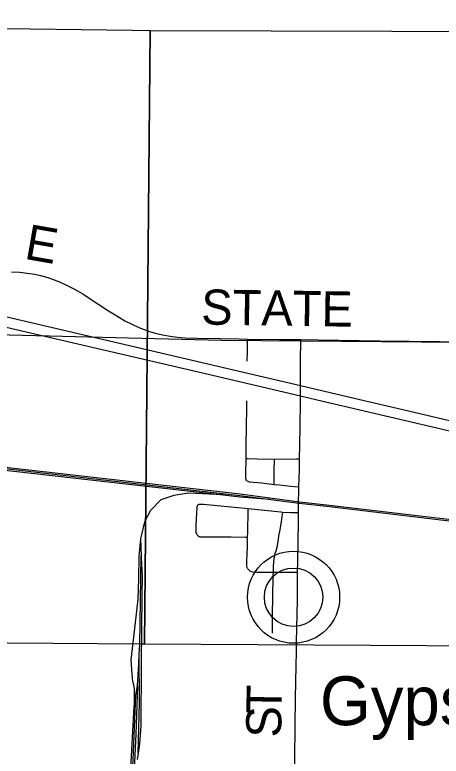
# Model space of a CAD drawing. Extents: x 63.4 to 97.4, y 0.4 to 22.4.
# Drawn here: x 66.497 to 67.186, y 15.396 to 16.594 of the extents above; entities that cross this region are included whole.
import ezdxf

# ---------------------------------------------------------------- set-up
doc = ezdxf.new("R2010")
doc.units = 0
for name, color, linetype in [('GM_X_County_Road', 7, 'Continuous'), ('GM_X_County_Road_Text', 7, 'Continuous'), ('GM_X_Rail_Line', 7, 'Continuous'), ('GM_X_Section', 7, 'Continuous'), ('GM_X_State_Route', 7, 'Continuous'), ('GM_X_Township_Road', 7, 'Continuous'), ('GM_X_Unincorporated', 7, 'Continuous'), ('GM_X_Unincorporated_Location', 7, 'Continuous'), ('GM_X_Unincorporated_Text', 7, 'Continuous')]:
    doc.layers.add(name, color=color, linetype=linetype)

msp = doc.modelspace()

# ---------------------------------------------------------------- linework, layer by layer
at = {"layer": 'GM_X_County_Road'}
for points in [[(66.4923, 16.1792), (66.5048, 16.1785), (66.5172, 16.1771), (66.5295, 16.175), (66.5387, 16.173), (66.5507, 16.1697), (66.5596, 16.1668), (66.5684, 16.1633), (66.5798, 16.1582), (66.5936, 16.1511), (66.6072, 16.1434), (66.6178, 16.1367), (66.6488, 16.116), (66.662, 16.1078), (66.6754, 16.1001), (66.6864, 16.0943), (66.6977, 16.0892), (66.7063, 16.0857), (66.7151, 16.0827), (66.724, 16.0801), (66.7361, 16.0772), (66.7483, 16.0749), (66.7605, 16.0732), (66.7729, 16.0722), (66.7915, 16.0716), (66.8288, 16.0712), (66.8599, 16.0706), (66.8734, 16.0704)], [(66.8734, 16.0704), (66.9253, 16.0698), (66.9501, 16.0695), (66.9594, 16.0695)], [(66.9575, 15.877), (66.958, 15.8999), (66.9582, 15.9278), (66.9588, 15.9711), (66.9588, 15.9785), (66.9589, 15.9953), (66.9589, 16.0178), (66.9592, 16.0364), (66.9594, 16.067), (66.9594, 16.0695)], [(66.9594, 16.0695), (66.9875, 16.0692), (67.087, 16.0673), (67.2799, 16.0651), (67.3097, 16.0648)], [(66.9565, 15.8314), (66.9572, 15.8595), (66.9575, 15.877)], [(66.9555, 15.7901), (66.9557, 15.8005), (66.9565, 15.8314)], [(66.9544, 15.694), (66.9549, 15.7105), (66.9555, 15.7757), (66.9555, 15.7901)], [(66.9526, 15.5807), (66.954, 15.6491), (66.9544, 15.694)], [(66.9518, 15.5428), (66.9523, 15.5646), (66.9526, 15.5807)], [(66.9495, 15.3439), (66.95, 15.3907), (66.9503, 15.4464), (66.9508, 15.4902), (66.9518, 15.5428)]]:
    msp.add_lwpolyline(points, dxfattribs=at)
at = {"layer": 'GM_X_Rail_Line'}
for p, q in [((66.7006, 15.7474), (66.7013, 15.7201)), ((66.6932, 15.4952), (66.6956, 15.5099)), ((66.6903, 15.4767), (66.6932, 15.4952)), ((66.6967, 15.4016), (66.6951, 15.3913))]:
    msp.add_line(p, q, dxfattribs=at)
for points in [[(65.5072, 16.0914), (66.1191, 16.083), (66.4239, 16.0787), (66.8313, 16.0688), (67.543, 16.0626), (67.9702, 16.0577), (68.6101, 16.2463), (69.1053, 16.3972), (70.1929, 16.7393), (70.2646, 16.7591), (70.3642, 16.7634), (70.5898, 16.7764), (70.6857, 16.8302), (70.7827, 16.8988), (71.2174, 17.2501), (71.5086, 17.4876), (71.6576, 17.6039), (72.13, 17.975), (72.3072, 18.116)], [(66.0355, 15.9113), (66.4667, 15.8604), (66.8342, 15.8186)], [(66.467, 15.8627), (66.8611, 15.8179), (66.9571, 15.8051), (67.0056, 15.7998), (67.2846, 15.7667), (67.4867, 15.743), (67.6241, 15.7268), (67.881, 15.6968), (67.9851, 15.6843), (68.0666, 15.6747), (68.1054, 15.67), (68.1409, 15.665)], [(66.4673, 15.865), (66.8614, 15.8202), (66.9574, 15.8074), (67.0058, 15.8021), (67.2848, 15.769), (67.487, 15.7453), (67.6243, 15.7291), (67.8813, 15.6991), (67.9854, 15.6866), (68.0669, 15.677), (68.1057, 15.6723), (68.1412, 15.6673)], [(66.8342, 15.8186), (66.7781, 15.8212), (66.7542, 15.8179), (66.7333, 15.8106), (66.7166, 15.7932), (66.7069, 15.7752), (66.7006, 15.7474)], [(66.8342, 15.8186), (66.8608, 15.8156), (66.9096, 15.8115)], [(66.7006, 15.7474), (66.6979, 15.719), (66.697, 15.6834), (66.6963, 15.6504), (66.6892, 15.5888), (66.6848, 15.5522), (66.6869, 15.5215), (66.6902, 15.5057), (66.6903, 15.4767)], [(66.7013, 15.7201), (66.7014, 15.7162), (66.703, 15.6867), (66.7027, 15.6572), (66.7018, 15.546), (66.701, 15.4457), (66.6989, 15.4162), (66.6967, 15.4016)], [(66.6985, 15.5611), (66.6992, 15.5764), (66.7013, 15.7201)], [(66.6956, 15.5099), (66.6978, 15.5456), (66.6985, 15.5611)], [(66.6967, 15.4016), (66.6986, 15.4828), (66.6985, 15.5611)], [(66.6956, 15.5099), (66.693, 15.4323), (66.6865, 15.2966), (66.6879, 15.261), (66.6871, 15.2203)], [(66.6845, 15.2433), (66.6841, 15.2852), (66.6848, 15.3279), (66.6886, 15.3908), (66.6932, 15.4952)], [(66.6845, 15.2433), (66.682, 15.2638), (66.6816, 15.3209), (66.6842, 15.367), (66.6903, 15.4767)]]:
    msp.add_lwpolyline(points, dxfattribs=at)
at = {"layer": 'GM_X_Section'}
for points in [[(66.6878, 16.5693), (66.716, 16.5687), (66.7072, 15.5775), (66.7036, 15.5772), (65.6882, 15.5852), (65.6938, 16.5825)], [(67.725, 16.5661), (67.7104, 15.5714), (66.7072, 15.5775), (66.716, 16.5687), (67.6925, 16.5663)]]:
    msp.add_lwpolyline(points, close=True, dxfattribs=at)
at = {"layer": 'GM_X_State_Route'}
for points in [[(65.6038, 16.2956), (65.6724, 16.2794), (65.7663, 16.2577), (65.9296, 16.2191), (66.0598, 16.1888), (66.329, 16.126), (66.3474, 16.1217), (66.4927, 16.0876), (66.7984, 16.0161), (66.9588, 15.9785), (66.986, 15.9721), (67.2462, 15.9113), (67.2796, 15.9042), (67.2979, 15.9007), (67.3163, 15.8979), (67.3379, 15.8952), (67.3595, 15.8931), (67.3812, 15.8916), (67.4091, 15.8905), (67.4473, 15.8897)], [(66.4824, 16.1066), (66.9589, 15.9953), (67.0548, 15.9729), (67.1244, 15.9564), (67.2365, 15.9302), (67.2668, 15.9234), (67.2943, 15.9179), (67.3158, 15.9143), (67.3343, 15.9118), (67.356, 15.9097), (67.3809, 15.9078), (67.4058, 15.9067), (67.4649, 15.9054), (67.5385, 15.9041), (67.5418, 15.9041), (67.5848, 15.9026), (67.6594, 15.901), (67.7848, 15.8983)]]:
    msp.add_lwpolyline(points, dxfattribs=at)
at = {"layer": 'GM_X_Township_Road'}
msp.add_line((66.8709, 15.8516), (66.8711, 15.8773), dxfattribs=at)
for points in [[(66.873, 16.0347), (66.8732, 16.0497), (66.8735, 16.06), (66.8735, 16.0659), (66.8734, 16.0704)], [(66.8711, 15.8773), (66.8713, 15.899), (66.8723, 15.9595), (66.8725, 15.9707)], [(66.8711, 15.8773), (66.8746, 15.8773), (66.8897, 15.8771), (66.9168, 15.8766)], [(66.9165, 15.8356), (66.9166, 15.8387), (66.9167, 15.8428), (66.9167, 15.8577), (66.9168, 15.8766)], [(66.9168, 15.8766), (66.9524, 15.877), (66.9575, 15.877)], [(66.8721, 15.8414), (66.8713, 15.8428), (66.871, 15.844), (66.8709, 15.8453), (66.8709, 15.8466), (66.8709, 15.8516)], [(66.8721, 15.8414), (66.8737, 15.8406), (66.8751, 15.8401), (66.8768, 15.8399), (66.8965, 15.8379), (66.9165, 15.8356)], [(66.9165, 15.8356), (66.9252, 15.8347), (66.9433, 15.8328), (66.9565, 15.8314)], [(66.7916, 15.7547), (66.791, 15.7563), (66.7906, 15.7581), (66.7903, 15.7597), (66.7903, 15.7614), (66.7906, 15.769), (66.7922, 15.799), (66.7923, 15.8001), (66.7924, 15.8009), (66.7926, 15.8016), (66.7929, 15.8022), (66.7939, 15.8032)], [(66.7939, 15.8032), (66.7955, 15.8037), (66.7971, 15.8038), (66.8025, 15.8034), (66.8524, 15.7987), (66.8744, 15.7965)], [(66.8736, 15.7503), (66.8738, 15.7579), (66.8744, 15.7943), (66.8744, 15.7965)], [(66.8744, 15.7965), (66.9272, 15.7912), (66.9307, 15.7909)], [(66.9153, 15.6939), (66.9156, 15.7033), (66.9165, 15.7156), (66.9173, 15.7206), (66.9183, 15.7247), (66.9198, 15.7285), (66.9215, 15.7343), (66.9225, 15.7394), (66.9246, 15.755), (66.9259, 15.7624), (66.9287, 15.7788), (66.9301, 15.7873), (66.9307, 15.7909)], [(66.9307, 15.7909), (66.9427, 15.79), (66.949, 15.79), (66.9555, 15.7901)], [(66.7916, 15.7547), (66.7926, 15.7534), (66.7937, 15.7524), (66.7951, 15.7516), (66.7965, 15.7511), (66.7994, 15.7507), (66.8031, 15.7507), (66.8217, 15.7508), (66.847, 15.7506), (66.8701, 15.7504), (66.8736, 15.7503)], [(66.874, 15.6992), (66.8729, 15.7013), (66.8723, 15.7035), (66.8722, 15.7054), (66.8722, 15.7095), (66.8725, 15.7146), (66.8727, 15.72), (66.8733, 15.7382), (66.8736, 15.7503)], [(66.874, 15.6992), (66.8756, 15.6973), (66.8773, 15.696), (66.8795, 15.6949), (66.8822, 15.6943), (66.8884, 15.6939), (66.9153, 15.6939)], [(66.9139, 15.595), (66.9137, 15.6187), (66.9138, 15.6253), (66.9143, 15.6538), (66.9151, 15.6879), (66.9153, 15.6939)], [(66.9153, 15.6939), (66.9452, 15.6939), (66.9484, 15.6939), (66.9544, 15.694)]]:
    msp.add_lwpolyline(points, dxfattribs=at)
at = {"layer": 'GM_X_Unincorporated'}
for radius in [0.0744, 0.0472]:
    msp.add_circle((66.9478, 15.6533), radius, dxfattribs=at)
at = {"layer": 'GM_X_Unincorporated_Location'}
msp.add_line((66.9478, 15.6533), (66.9478, 15.6533), dxfattribs=at)

# ---------------------------------------------------------------- texts
at = {"layer": 'GM_X_County_Road_Text'}
for s, height, rotation, p in [('E', 0.0568, 350.0854, (66.5113, 16.2003)), ('STATE', 0.05682, 359.1575, (66.7983, 16.0939)), ('T', 0.0568, 88.9628, (66.9281, 15.4646)), ('S', 0.0568, 89.962, (66.9281, 15.4266))]:
    msp.add_text(s, height=height, rotation=rotation, dxfattribs=at).set_placement(p)
at = {"layer": 'GM_X_Unincorporated_Text'}
msp.add_text('Gypsum', height=0.07898, rotation=0, dxfattribs=at).set_placement((66.9904, 15.4465))

doc.saveas('drawing.dxf')
